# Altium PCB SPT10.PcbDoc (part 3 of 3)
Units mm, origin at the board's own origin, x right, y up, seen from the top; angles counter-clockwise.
Board outline 194 x 91 mm, 4 copper layers (Top Layer, Mid-Layer 8, Mid-Layer 28, Bottom Layer); 266 components, 1 nets, 803 pads, 630 vias.
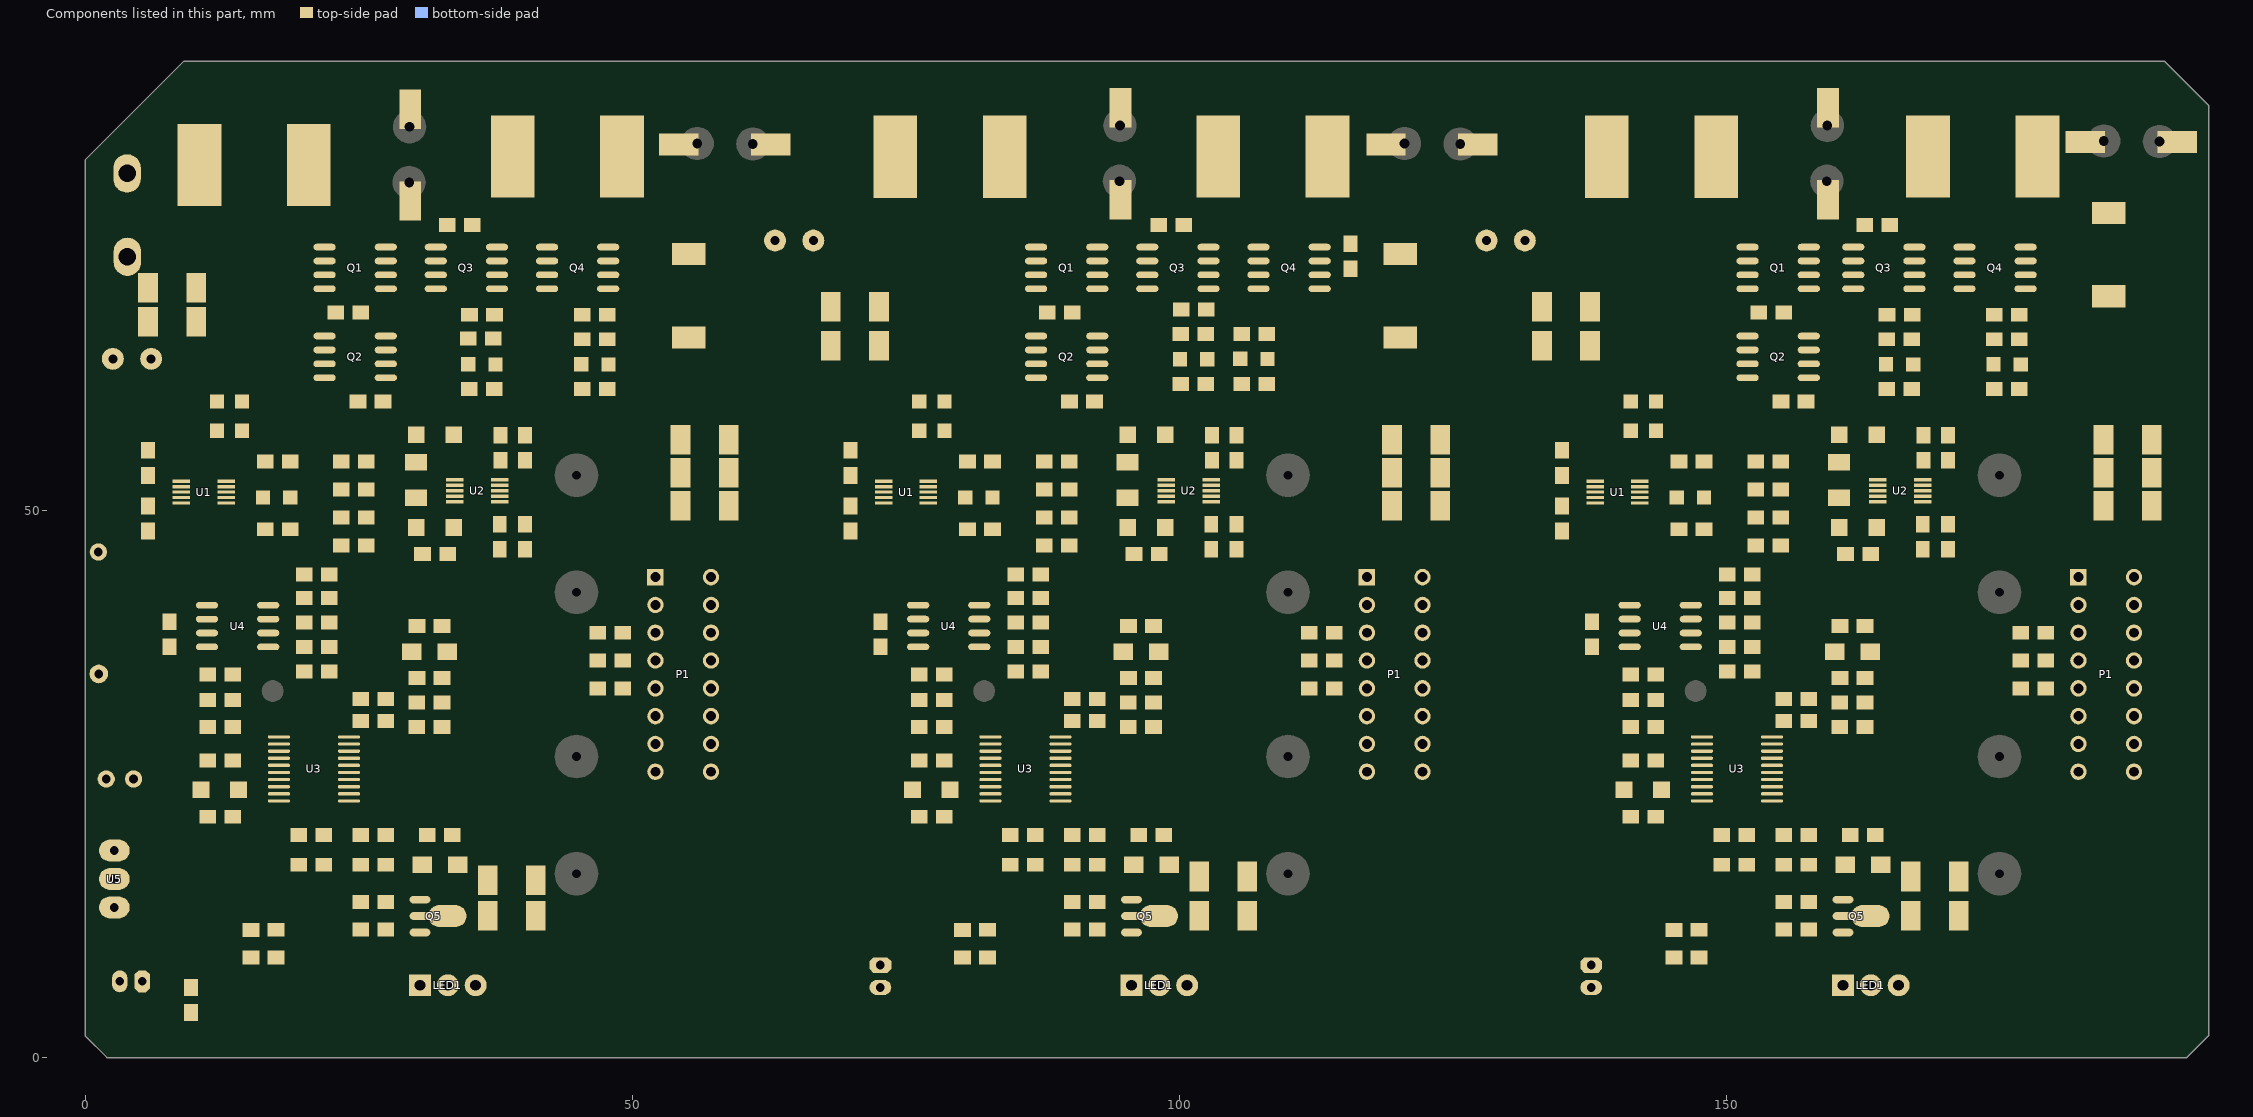
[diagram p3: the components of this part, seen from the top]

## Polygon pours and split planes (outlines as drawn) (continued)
no net on Bottom Layer "Top-No Net" (hatched 90Degree grid 0.1 track 0.15, remove dead copper, pour order 185): 175.505,86.71 185.76,86.71 186.78,85.69 186.78,80.67 188.03,79.42 188.03,71.88 187.41,71.26 181.67,71.26 181.22,71.71 181.22,73.32 180.23,74.31 175.355,74.31 174.825,74.84 174.825,86.03
no net on Bottom Layer "Top-No Net" (hatched 90Degree grid 0.1 track 0.15, remove dead copper, pour order 182): 165.69,86.73 173.125,86.73 173.75,86.105 173.75,67.61 173.03,66.89 165.57,66.89 164.79,67.67 164.79,85.83
no net on Bottom Solder "Top-No Net" (hatched 90Degree grid 0.1 track 0.15, remove dead copper): 43.27,86.13 43.73,85.67 43.73,70.52 43.202,69.992 35.698,69.992 35.13,70.56 35.13,85.76 35.5,86.13
no net on Bottom Solder "Top-No Net" (hatched 90Degree grid 0.1 track 0.15, remove dead copper): 46.32,86.13 56.97,86.13 57.56,85.54 57.56,71.87 57.17,71.48 53.14,71.48 52.73,71.89 52.73,73.28 50.89,75.12 47.55,75.12 46.63,76.04 45.58,77.09 45.58,78.51 45.58,85.64 46.07,86.13
no net on Bottom Solder "Top-No Net" (hatched 90Degree grid 0.1 track 0.15, remove dead copper): 27.13,82.1 32.82,82.1 33.26,81.66 33.26,70.27 32.9,69.91 27.03,69.91 26.26,70.68 26.26,81.64 26.69,82.07 26.72,82.1 27.13,82.1
no net on Bottom Solder "Top-No Net" (hatched 90Degree grid 0.1 track 0.15, remove dead copper): 16.09,85.73 23.35,85.73 23.9,85.18 23.9,69.192 23.25,68.542 16.138,68.542 15.58,69.1 15.58,85.22
no net on Bottom Solder "Top-No Net" (hatched 90Degree grid 0.1 track 0.15, remove dead copper): 80.267,85.42 88.132,85.42 88.51,85.042 88.51,63.03 87.6,62.12 80.34,62.12 79.467,62.993 79.467,84.63 80.267,85.43
no net on Bottom Solder "Top-No Net" (hatched 90Degree grid 0.1 track 0.15, remove dead copper): 101.35,85.22 107.39,85.22 108.23,84.38 108.23,71.3 107.68,70.75 101.24,70.75 100.65,71.34 100.65,84.52
no net on Bottom Solder "Top-No Net" (hatched 90Degree grid 0.1 track 0.15, remove dead copper): 177.042,85.84 185.308,85.842 186.01,85.14 186.01,79.777 187.5,78.287 187.5,72.012 187.03,71.542 182.178,71.542 181.89,71.83 181.89,73.48 180.628,74.742 178.025,74.742 176.38,76.387 176.38,85.179
no net on Bottom Solder "Top-No Net" (hatched 90Degree grid 0.1 track 0.15, remove dead copper): 166.27,85.22 172.54,85.22 173.23,84.53 173.23,68.142 172.63,67.542 166.55,67.542 165.65,68.442 165.65,84.6
no net on Bottom Solder "Top-No Net" (hatched 90Degree grid 0.1 track 0.15, remove dead copper): 112.332,85.842 121.648,85.842 122.5,84.99 122.5,72.012 122.03,71.542 118.38,71.542 117.98,71.942 117.98,73.582 116.82,74.742 113.025,74.742 111.57,76.197 111.57,85.08
no net on Bottom Solder "Top-No Net" (hatched 90Degree grid 0.1 track 0.15, remove dead copper): 90.967,82.2 97.82,82.2 98.31,81.71 98.31,70.423 97.867,69.98 91.84,69.98 90.39,71.43 90.39,81.623
no net on Bottom Solder "Top-No Net" (hatched 90Degree grid 0.1 track 0.15, remove dead copper): 155.967,82.2 162.74,82.2 163.31,81.63 163.31,70.423 162.867,69.98 156.85,69.98 155.39,71.44 155.39,81.623
no net on Bottom Solder "Top-No Net" (hatched 90Degree grid 0.1 track 0.15, remove dead copper): 12.77,85.65 13.09,85.33 13.09,69.16 12.6,68.67 9.82,68.67 9.47,69.02 9.47,85.17 9.95,85.65
no net on Bottom Solder "Top-No Net" (hatched 90Degree grid 0.1 track 0.15, remove dead copper): 71.03,85.33 76.47,85.33 77.13,84.67 77.13,78.7 77.13,64.21 76.39,63.47 72.59,63.47 71.2,63.47 70.46,64.21 70.46,84.76 71.03,85.33
no net on Bottom Solder "Top-No Net" (hatched 90Degree grid 0.1 track 0.15, remove dead copper): 136.38,89.95 141.21,89.95 141.74,89.42 142.03,89.13 142.03,88.27 142.03,64.42 141.13,63.52 136.21,63.52 135.48,64.25 135.48,89.33 136.1,89.95
no net on Bottom Solder "Top-No Net" (hatched 90Degree grid 0.1 track 0.15, remove dead copper): 145.43,89.91 152.5,89.91 153.51,88.9 153.51,63.03 152.6,62.12 145.34,62.12 144.467,62.993 144.467,88.947

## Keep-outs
Keep-Out Layer:
  circle w0.2: c183.5,66 r1
  circle w0.2: c188.5,66 r1.5
  circle w0.2: c112,66 r1.5
  circle w0.2: c188.5,4 r1.5
  circle w0.2: c112,4 r1.5
  circle w0.2: c22.5,4 r1
  circle w0.2: c17.5,66 r1.5
  circle w0.2: c17.5,4 r1.5
  lines w0.2: 0,2 2,0 192,0 194,2 194,85 188,91 9,91 0,82 0,2 ; 187,91 187,91

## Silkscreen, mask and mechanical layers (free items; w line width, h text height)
Top Overlay:
  drawing of 3524 lines, arcs and shapes, not listed
  text "BAT-" at 43.55,56.58 h0.8
  text "BAT-" at 108.55,56.58 h0.8
  text "BAT-" at 173.55,56.58 h0.8
  text "VSEL" at 43.7,45.51 h0.8
  text "VSEL" at 108.7,45.51 h0.8
  text "VSEL" at 173.7,45.51 h0.8
  text "TX" at 16.3,34.73 h1
  text "TX" at 81.29,34.63 h1
  text "TX" at 146.29,34.63 h1
  text "T" at 109.61,31.2 h0.8
  text "T" at 174.61,31.2 h0.8
  text "T" at 44.62,30.67 h0.8
  text "BAT+" at 43.29,19.95 h0.8
  text "BAT+" at 108.29,19.95 h0.8
  text "BAT+" at 173.29,19.95 h0.8
  text "GREEN" at 38.93,6.32 h0.8
  text "GREEN" at 104.18,6.32 h0.8
  text "GREEN" at 169.75,6.18 h0.8
  text "SPT10-V1.3" at 113.99,5.09 h2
